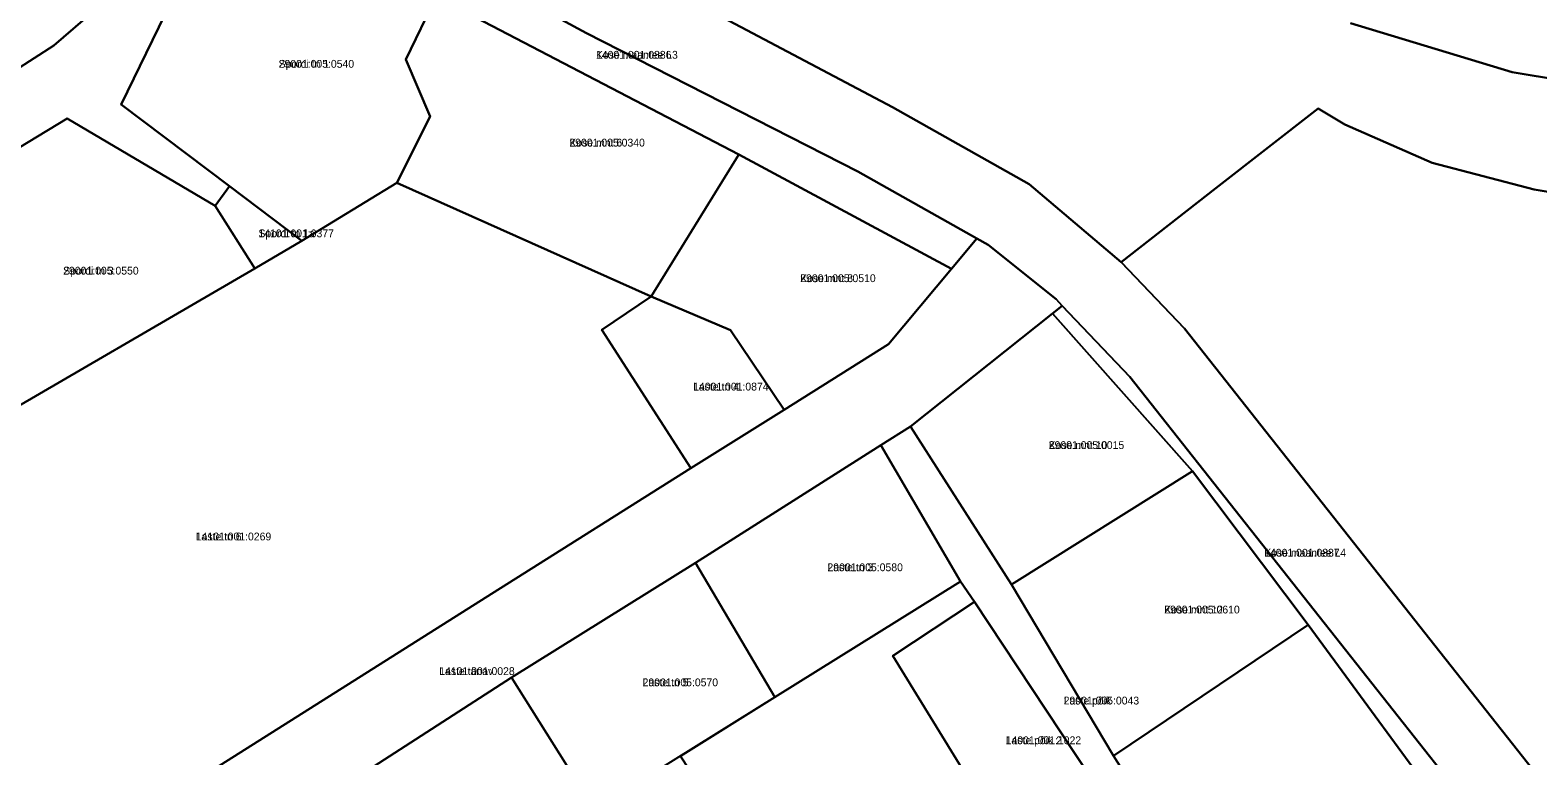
# Model space of a CAD drawing. Extents: x 566437 to 602312, y 6556921 to 6586574.
# Drawn here: x 575929.9 to 576219.6, y 6577681.1 to 6577820.6 of the extents above; entities that cross this region are included whole.
import ezdxf

# ---------------------------------------------------------------- set-up
doc = ezdxf.new("R2010")
doc.units = 0
for name, color, linetype in [('L_AADRESS', 7, 'Continuous'), ('PIIR', 7, 'Continuous'), ('TUNNUS', 7, 'Continuous')]:
    doc.layers.add(name, color=color, linetype=linetype)

msp = doc.modelspace()

# ---------------------------------------------------------------- linework, layer by layer
at = {"layer": 'PIIR'}
for points in [[(575914.42, 6577882.76), (575959.12, 6577858.6), (575946.76, 6577831.44), (575942.32, 6577824.42), (575934.48, 6577817.6), (575919.29, 6577807.9), (575883.57, 6577827.35)], [(575799.52, 6577754.47), (575818.69, 6577743.86), (575867.62, 6577774.9), (575871.03, 6577777.08), (575919.29, 6577807.9), (575934.48, 6577817.6), (575942.32, 6577824.42), (575946.76, 6577831.44), (575959.12, 6577858.6), (575960.37, 6577861.34), (575971.27, 6577855.43), (575967.88, 6577848.45), (575947.38, 6577806.27), (575968.21, 6577790.58), (575965.45, 6577786.8), (575937.06, 6577803.56), (575897.69, 6577779.77), (575851.77, 6577751.73), (575852.31, 6577750.92), (575822.08, 6577730.9), (575821.05, 6577726.98)], [(576111.82, 6577780.55), (576106.96, 6577774.73), (576066.11, 6577796.68), (576007.96, 6577827.04), (575967.88, 6577848.45), (575971.27, 6577855.43), (576036.81, 6577819.97), (576088.98, 6577793.42)], [(575967.88, 6577848.45), (576007.96, 6577827.04), (576002.1, 6577814.93), (576006.75, 6577803.99), (576000.38, 6577791.22), (575982.13, 6577780.1), (575968.21, 6577790.58), (575947.38, 6577806.27)], [(576066.11, 6577796.68), (576049.23, 6577769.36), (576000.38, 6577791.22), (576006.75, 6577803.99), (576002.1, 6577814.93), (576007.96, 6577827.04)], [(575897.69, 6577779.77), (575937.06, 6577803.56), (575965.45, 6577786.8), (575973.08, 6577774.74), (575919.58, 6577743.64)], [(576064.51, 6577762.91), (576049.23, 6577769.36), (576066.11, 6577796.68), (576106.96, 6577774.73), (576094.84, 6577760.23), (576074.81, 6577747.63)], [(575892.66, 6577706.65), (575884.17, 6577719.47), (575919.58, 6577743.64), (575973.08, 6577774.74), (575982.13, 6577780.1), (576000.38, 6577791.22), (576049.23, 6577769.36), (576039.79, 6577762.97), (576056.89, 6577736.43), (576020.27, 6577713.34), (575926.11, 6577653.83), (575913.93, 6577673.08), (575903.24, 6577689.92)], [(575973.08, 6577774.74), (575965.45, 6577786.8), (575968.21, 6577790.58), (575982.13, 6577780.1)], [(575957.12, 6577653.94), (575935.45, 6577639.5), (575892.42, 6577612.75), (575883.63, 6577626.98), (575926.11, 6577653.83), (576020.27, 6577713.34), (576056.89, 6577736.43), (576074.81, 6577747.63), (576094.84, 6577760.23), (576106.96, 6577774.73), (576111.82, 6577780.55), (576113.97, 6577779.34), (576127.04, 6577768.85), (576128.2, 6577767.59), (576126.36, 6577766.11), (576099.04, 6577744.42), (576093.35, 6577740.83), (576057.79, 6577718.18), (576022.41, 6577696.17), (575993.83, 6577677.75), (575978.79, 6577668.22)], [(576074.81, 6577747.63), (576056.89, 6577736.43), (576039.79, 6577762.97), (576049.23, 6577769.36), (576064.51, 6577762.91)], [(576207.7, 6577669.35), (576204.26, 6577667.11), (576175.5, 6577706.32), (576153.23, 6577735.81), (576126.36, 6577766.11), (576128.2, 6577767.59), (576141.22, 6577753.94), (576206.98, 6577670.69)], [(576126.36, 6577766.11), (576153.23, 6577735.81), (576118.48, 6577714.05), (576099.04, 6577744.42)], [(576093.35, 6577740.83), (576099.04, 6577744.42), (576118.48, 6577714.05), (576138.05, 6577681.15), (576163.66, 6577640.63), (576158.59, 6577637.57), (576142.12, 6577664.25), (576139.02, 6577668.9), (576111.36, 6577710.69), (576108.67, 6577714.61)], [(576108.67, 6577714.61), (576072.98, 6577692.38), (576057.79, 6577718.18), (576093.35, 6577740.83)], [(576175.5, 6577706.32), (576138.05, 6577681.15), (576118.48, 6577714.05), (576153.23, 6577735.81)], [(576057.79, 6577718.18), (576072.98, 6577692.38), (576038.36, 6577670.81), (576022.41, 6577696.17)], [(576121.88, 6577657.71), (576085.9, 6577634.01), (576054.86, 6577681.09), (576072.98, 6577692.38), (576108.67, 6577714.61), (576111.36, 6577710.69), (576095.69, 6577700.37)], [(576139.02, 6577668.9), (576121.88, 6577657.71), (576095.69, 6577700.37), (576111.36, 6577710.69)], [(576204.26, 6577667.11), (576163.66, 6577640.63), (576138.05, 6577681.15), (576175.5, 6577706.32)], [(576022.41, 6577696.17), (576038.36, 6577670.81), (576069.23, 6577623.6), (576039.56, 6577604.97), (575993.83, 6577677.75)]]:
    msp.add_lwpolyline(points, close=True, dxfattribs=at)
for points in [[(575991.44, 6577860.93), (576095.59, 6577805.76), (576121.84, 6577790.98), (576139.55, 6577776.01), (576151.7, 6577763.24), (576218.61, 6577678.56), (576248.16, 6577623.5), (576275.63, 6577565.39), (576304.7, 6577497.45), (576310.07, 6577477.46), (576311.83, 6577470.8), (576312.75, 6577468.55), (576342.78, 6577388.3)], [(576233.6, 6577787.54), (576218.92, 6577789.93), (576199.32, 6577795.07), (576182.51, 6577802.45), (576177.37, 6577805.48), (576157.74, 6577790.18), (576139.55, 6577776.01), (576121.84, 6577790.98), (576095.59, 6577805.76), (575991.44, 6577860.93)], [(576320.8, 6577407.04), (576299.03, 6577465.13), (576295.24, 6577478.98), (576291.81, 6577491.53), (576291.47, 6577492.76), (576262.84, 6577559.68), (576241.04, 6577605.81), (576237.16, 6577614.03), (576235.63, 6577617.27), (576212.64, 6577660.14), (576207.7, 6577669.35), (576206.98, 6577670.69), (576141.22, 6577753.94), (576128.2, 6577767.59), (576127.04, 6577768.85), (576113.97, 6577779.34), (576111.82, 6577780.55), (576088.98, 6577793.42), (576036.81, 6577819.97), (575971.27, 6577855.43)], [(576183.62, 6577821.88), (576214.68, 6577812.52), (576253.36, 6577806.06), (576293.09, 6577806.24), (576315.39, 6577810.04), (576371.73, 6577824.75)], [(576371.73, 6577824.75), (576315.39, 6577810.04), (576293.09, 6577806.24), (576253.36, 6577806.06), (576214.68, 6577812.52), (576183.62, 6577821.88)], [(576248.16, 6577623.5), (576218.61, 6577678.56), (576151.7, 6577763.24), (576139.55, 6577776.01), (576157.74, 6577790.18), (576177.37, 6577805.48), (576182.51, 6577802.45), (576199.32, 6577795.07), (576218.92, 6577789.93), (576233.6, 6577787.54)]]:
    msp.add_lwpolyline(points, dxfattribs=at)

# ---------------------------------------------------------------- texts
at = {"layer": 'L_AADRESS'}
for s, p in [('Kose maantee L3', (576038.64, 6577815.08)), ('Spordi tn 1', (575977.67, 6577813.34)), ('Kose mnt 6', (576033.53, 6577798.2)), ('Spordi tn 1a', (575973.79, 6577780.77)), ('Spordi tn 3', (575936.27, 6577773.6)), ('Kose mnt 8', (576077.88, 6577772.15)), ('Laste tn 4', (576057.3, 6577751.32)), ('Kose mnt 10', (576125.63, 6577740.08)), ('Laste tn 6', (575961.74, 6577722.52)), ('Kose maantee L4', (576167.03, 6577719.4)), ('Laste tn 3', (576083.11, 6577716.6)), ('Kose mnt 12', (576147.83, 6577708.48)), ('Laste tänav', (576008.52, 6577696.65)), ('Laste tn 5', (576047.6, 6577694.49)), ('Laste põik', (576128.5, 6577690.99)), ('Laste põik 2', (576117.36, 6577683.36))]:
    msp.add_text(s, height=1.5, dxfattribs=at).set_placement(p)
at = {"layer": 'TUNNUS'}
for s, p in [('14001:001:0886', (576038.64, 6577815.08)), ('29001:005:0540', (575977.67, 6577813.34)), ('29001:005:0340', (576033.53, 6577798.2)), ('14101:001:0377', (575973.79, 6577780.77)), ('29001:005:0550', (575936.27, 6577773.6)), ('29001:005:0510', (576077.88, 6577772.15)), ('14001:001:0874', (576057.3, 6577751.32)), ('29001:005:0015', (576125.63, 6577740.08)), ('14101:001:0269', (575961.74, 6577722.52)), ('14001:001:0887', (576167.03, 6577719.4)), ('29001:005:0580', (576083.11, 6577716.6)), ('29001:005:0610', (576147.83, 6577708.48)), ('14101:001:0028', (576008.52, 6577696.65)), ('29001:005:0570', (576047.6, 6577694.49)), ('29001:005:0043', (576128.5, 6577690.99)), ('14001:001:1022', (576117.36, 6577683.36))]:
    msp.add_text(s, height=1.5, dxfattribs=at).set_placement(p)

doc.saveas('drawing.dxf')
